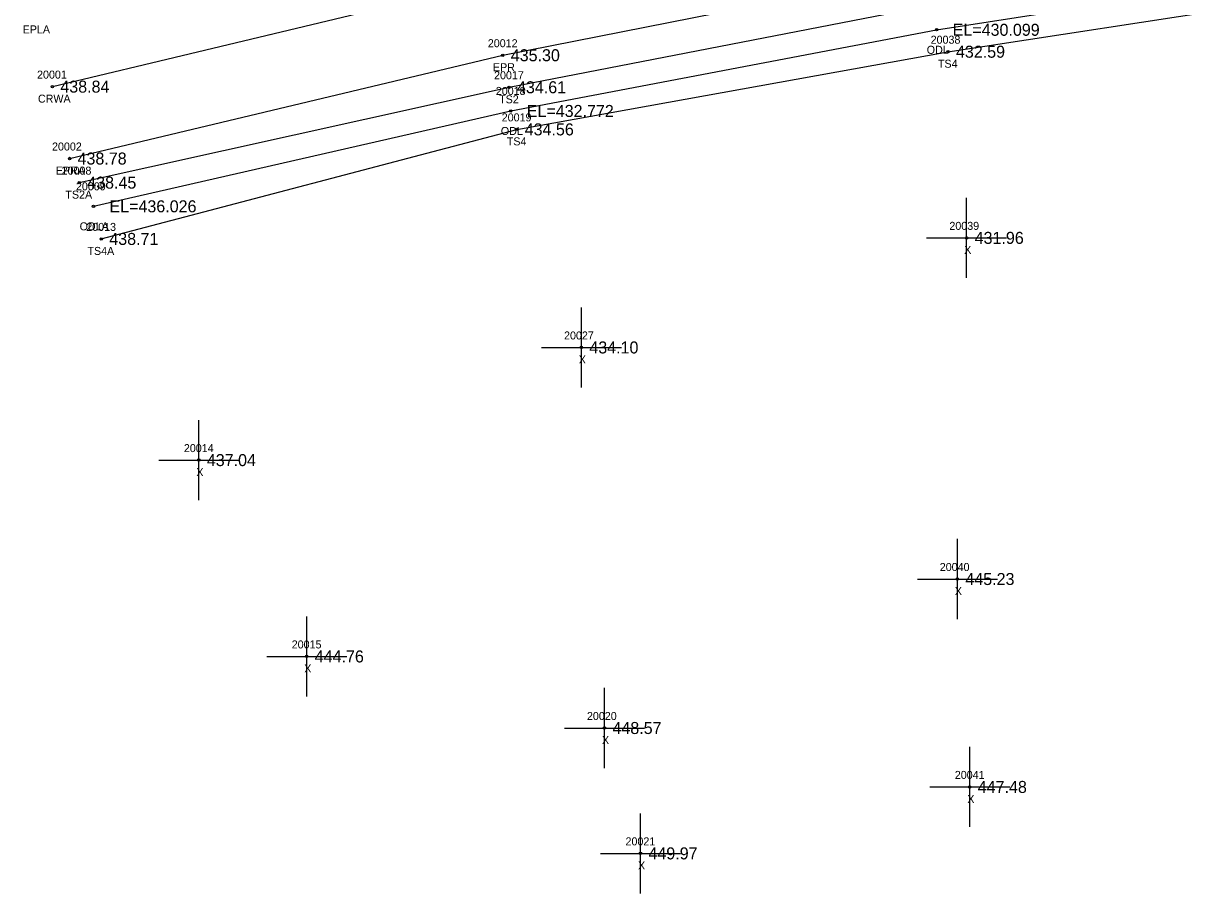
# Model space of a CAD drawing. Extents: x 2116373 to 2118139, y 979529 to 981026.
# Drawn here: x 2116410.6 to 2116558, y 979529.4 to 979638.1 of the extents above; entities that cross this region are included whole.
import ezdxf

# ---------------------------------------------------------------- set-up
doc = ezdxf.new("R2010")
doc.units = 0
for name, color, linetype in [('RD_DTM_BkLn1', 7, 'Continuous'), ('RD_DTM_BkLn2', 7, 'Continuous'), ('RD_DTM_BkLn_txCode', 7, 'Continuous'), ('RD_EX_H2O', 7, 'Continuous'), ('RD_EX_H2O_txCode', 7, 'Continuous'), ('RD_EX_Misc', 7, 'Continuous'), ('RD_EX_Misc_txCode', 7, 'Continuous'), ('RD_EX_Road', 7, 'Continuous'), ('RD_EX_Road_txCode', 7, 'Continuous'), ('RD_EX_TX_H2O_ELEV', 7, 'Continuous'), ('RD_EX_TX_Misc_ELEV', 7, 'Continuous'), ('RD_EX_TX_Road_ELEV', 7, 'Continuous'), ('RD_HC_Survey_ELEV', 7, 'Continuous'), ('RD_HC_Survey_txCode', 7, 'Continuous'), ('RD_SMD_Locator', 7, 'Continuous')]:
    doc.layers.add(name, color=color, linetype=linetype)

msp = doc.modelspace()

# ---------------------------------------------------------------- linework, layer by layer
at = {"layer": 'RD_DTM_BkLn1'}
msp.add_lwpolyline([(2116414.21, 979630.19), (2116468.62, 979643.23), (2116521.45, 979653.6), (2116618.87, 979670.38), (2116668.4, 979680.7), (2116717.3, 979694.48), (2116764.56, 979711.13), (2116810.15, 979729.38), (2116856.49, 979749.81), (2116900.74, 979773.15), (2116944.03, 979798.93), (2116982.75, 979824.6), (2117026.56, 979857.02), (2117064.34, 979888.81), (2117101.78, 979922.69), (2117176.3, 979989.4), (2117250.99, 980056.19), (2117326.56, 980126.36)], dxfattribs=at)
at = {"layer": 'RD_DTM_BkLn2'}
for points in [[(2116417.57, 979618.2), (2116471.29, 979630.11), (2116523.91, 979640.31), (2116563.87, 979646.21), (2116622.92, 979650.9), (2116673.37, 979660.68), (2116721.38, 979672.44), (2116775.31, 979687.3), (2116820.23, 979708.52), (2116865.35, 979734.51), (2116907.21, 979760.29), (2116934.42, 979772.82), (2116951.5, 979788.78), (2116990.39, 979814.35), (2117033.97, 979847.22), (2117071.26, 979879.46), (2117111.32, 979914.45), (2117184.14, 979980.37), (2117264.18, 980040.84), (2117335.34, 980108.05), (2117336.43, 980115.6)], [(2116420.33, 979611.17), (2116472.25, 979624.85), (2116526.15, 979634.55), (2116564.74, 979640.45), (2116627.58, 979623.31), (2116680.58, 979618.75), (2116744.33, 979647.79), (2116783.58, 979660.27), (2116799.87, 979666.49), (2116808.73, 979670.75)]]:
    msp.add_lwpolyline(points, dxfattribs=at)
at = {"layer": 'RD_EX_H2O'}
msp.add_lwpolyline([(2116419.35, 979615.24), (2116471.51, 979627.15), (2116524.74, 979637.29), (2116564.01, 979643.4), (2116629.25, 979631.55), (2116678.97, 979635.46), (2116738.46, 979663.21), (2116776.82, 979674.03), (2116792.52, 979682.03), (2116799, 979683.75), (2116807.27, 979675.26), (2116829.37, 979675.94), (2116879.68, 979679.78), (2116933.5, 979668.89), (2116988.71, 979660.02), (2117093.78, 979621.95), (2117143.56, 979603.85), (2117167, 979599.31)], dxfattribs=at)
at = {"layer": 'RD_EX_Misc'}
for p, q in [((2116528.49, 979606.3), (2116528.49, 979616.3)), ((2116523.49, 979611.3), (2116533.49, 979611.3)), ((2116480.33, 979592.61), (2116480.33, 979602.61)), ((2116475.33, 979597.61), (2116485.33, 979597.61)), ((2116432.52, 979578.54), (2116432.52, 979588.54)), ((2116427.52, 979583.54), (2116437.52, 979583.54)), ((2116527.33, 979563.69), (2116527.33, 979573.69)), ((2116522.33, 979568.69), (2116532.33, 979568.69)), ((2116446.01, 979554.02), (2116446.01, 979564.02)), ((2116441.01, 979559.02), (2116451.01, 979559.02)), ((2116483.22, 979545.08), (2116483.22, 979555.08)), ((2116478.22, 979550.08), (2116488.22, 979550.08)), ((2116528.88, 979537.72), (2116528.88, 979547.72)), ((2116523.88, 979542.72), (2116533.88, 979542.72)), ((2116487.72, 979529.42), (2116487.72, 979539.42)), ((2116482.72, 979534.42), (2116492.72, 979534.42))]:
    msp.add_line(p, q, dxfattribs=at)
at = {"layer": 'RD_EX_Road'}
msp.add_lwpolyline([(2116416.36, 979621.21), (2116470.51, 979634.11), (2116523.97, 979644.68), (2116620.55, 979661.21), (2116670.7, 979671.96), (2116720.65, 979685.84), (2116767.66, 979702.22), (2116814.07, 979721.02), (2116860.35, 979742.3), (2116904.9, 979765.18), (2116949.06, 979791.19), (2116988.09, 979817.15), (2117031.94, 979849.78), (2117069.79, 979881.53), (2117108.89, 979916.38), (2117182.06, 979982.67), (2117257.56, 980049.29), (2117334.73, 980117.38), (2117326.56, 980126.36)], dxfattribs=at)
at = {"layer": 'RD_SMD_Locator'}
for centre in [(2116524.74, 979637.29), (2116470.51, 979634.11), (2116526.15, 979634.55), (2116414.21, 979630.19), (2116471.29, 979630.11), (2116471.51, 979627.15), (2116472.25, 979624.85), (2116416.36, 979621.21), (2116417.57, 979618.2), (2116419.35, 979615.24), (2116528.49, 979611.3), (2116420.33, 979611.17), (2116480.33, 979597.61), (2116432.52, 979583.54), (2116527.33, 979568.69), (2116446.01, 979559.02), (2116483.22, 979550.08), (2116528.88, 979542.72), (2116487.72, 979534.42)]:
    msp.add_circle(centre, 0.15, dxfattribs=at)

# ---------------------------------------------------------------- texts
at = {"layer": 'RD_DTM_BkLn_txCode'}
for s, p in [('20038', (2116523.99, 979635.55)), ('TS4', (2116524.9, 979632.55)), ('20017', (2116469.42, 979631.11)), ('TS2', (2116470.05, 979628.11)), ('20019', (2116470.38, 979625.85)), ('TS4', (2116471.01, 979622.85)), ('20008', (2116415.37, 979619.2)), ('TS2A', (2116415.84, 979616.2)), ('20013', (2116418.45, 979612.17)), ('TS4A', (2116418.6, 979609.17))]:
    msp.add_text(s, height=1, dxfattribs=at).set_placement(p)
at = {"layer": 'RD_EX_H2O_txCode'}
for s, p in [('ODL', (2116523.5, 979634.29)), ('20018', (2116469.64, 979629.15)), ('ODL', (2116470.27, 979624.15)), ('20009', (2116417.16, 979617.24)), ('ODLA', (2116417.62, 979612.24))]:
    msp.add_text(s, height=1, dxfattribs=at).set_placement(p)
at = {"layer": 'RD_EX_Misc_txCode'}
for s, p in [('20039', (2116526.33, 979612.3)), ('X', (2116528.18, 979609.3)), ('20027', (2116478.17, 979598.61)), ('X', (2116480.01, 979595.61)), ('20014', (2116430.65, 979584.54)), ('X', (2116432.21, 979581.54)), ('20040', (2116525.13, 979569.69)), ('X', (2116527.01, 979566.69)), ('20015', (2116444.13, 979560.02)), ('X', (2116445.69, 979557.02)), ('20020', (2116481.03, 979551.08)), ('X', (2116482.91, 979548.08)), ('20041', (2116527.01, 979543.72)), ('X', (2116528.57, 979540.72)), ('20021', (2116485.85, 979535.42)), ('X', (2116487.41, 979532.42))]:
    msp.add_text(s, height=1, dxfattribs=at).set_placement(p)
at = {"layer": 'RD_EX_Road_txCode'}
for s, p in [('EPLA', (2116410.5, 979636.84)), ('20012', (2116468.64, 979635.11)), ('EPR', (2116469.28, 979632.11)), ('20002', (2116414.17, 979622.21)), ('EPRA', (2116414.65, 979619.21))]:
    msp.add_text(s, height=1, dxfattribs=at).set_placement(p)
at = {"layer": 'RD_EX_TX_H2O_ELEV'}
for s, p in [('EL=430.099', (2116526.74, 979636.54)), ('EL=432.772', (2116473.51, 979626.4)), ('EL=436.026', (2116421.35, 979614.49))]:
    msp.add_text(s, height=1.5, dxfattribs=at).set_placement(p)
at = {"layer": 'RD_EX_TX_Misc_ELEV'}
for s, p in [('432.59', (2116527.15, 979633.8)), ('434.61', (2116472.29, 979629.36)), ('434.56', (2116473.25, 979624.1)), ('438.45', (2116418.57, 979617.45)), ('438.71', (2116421.33, 979610.42)), ('431.96', (2116529.49, 979610.55)), ('434.10', (2116481.33, 979596.86)), ('437.04', (2116433.52, 979582.79)), ('445.23', (2116528.33, 979567.94)), ('444.76', (2116447.01, 979558.27)), ('448.57', (2116484.22, 979549.33)), ('447.48', (2116529.88, 979541.97)), ('449.97', (2116488.72, 979533.67))]:
    msp.add_text(s, height=1.5, dxfattribs=at).set_placement(p)
at = {"layer": 'RD_EX_TX_Road_ELEV'}
for s, p in [('435.30', (2116471.51, 979633.36)), ('438.78', (2116417.36, 979620.46))]:
    msp.add_text(s, height=1.5, dxfattribs=at).set_placement(p)
at = {"layer": 'RD_HC_Survey_ELEV'}
msp.add_text('438.84', height=1.5, dxfattribs=at).set_placement((2116415.21, 979629.44))
at = {"layer": 'RD_HC_Survey_txCode'}
for s, p in [('20001', (2116412.3, 979631.19)), ('CRWA', (2116412.41, 979628.19))]:
    msp.add_text(s, height=1, dxfattribs=at).set_placement(p)

doc.saveas('drawing.dxf')
